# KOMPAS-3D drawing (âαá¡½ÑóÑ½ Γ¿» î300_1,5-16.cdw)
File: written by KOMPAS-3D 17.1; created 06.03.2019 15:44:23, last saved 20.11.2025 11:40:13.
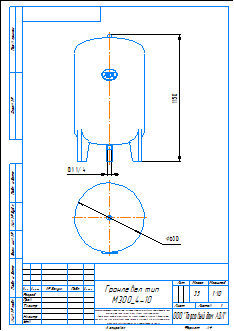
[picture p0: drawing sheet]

Sheet 1: A4, portrait

Title block, sheet 1: name: Гранлевел тип / М300_4-10; mass: 35; sheets: 1; sheet format: A4; stored path: C:\Users\kka\KOMPAS_Work\!Trash\ГРАНЛЕВЕЛ тип А Расширительный бак\KOMPAS 2D\Гранлевел тип А100_1,5-16.cdw

Views: Спереди 1, Спереди, Проекционный вид 2
Referenced files in C:\Users\mipv\Desktop\Тип А\SAT\: Гранлевел тип А300_4-10.a3d
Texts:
  kka
  adl
  Гранлевел тип А300_4-10
  Рама для чертежей
  Лит-Масса-Масштаб
  Материал-Предприятие
  Масштаб
  Изм.
  Лист
  № докум.
  Подп.
  Дата
  Лит.
  Разраб.
  Пров.
  Т.контр.
  Листов
  Внимание! Данный продукт является объектом авторского права ООО «Торговый Дом АДЛ».
  Запрещается изменение, копирование, распространение
  (в том числе путем копирования на другие сайты и ресурсы в Интернете)
  или любое иное использование информации и объектов без предварительного
  согласия правообладателя (ООО «Торговый Дом АДЛ»).
  Н.контр.
  Утв.
  ООО "Торговый дом АДЛ"
  Изменение
  Номер документа
  Подпись
  Обозначение документа
  Наименование изделия
  Масса изделия по ГОСТ 2.109-73
  Порядковый номер листа
  Общее количество листов в документе
  Характер работы, выполненной лицом, подписавшим документ
  Наименование или индекс предприятия, выпускающего документ
  Инв. № подл.
  Подп. и дата
  Взам. инв. №
  Инв. № дубл.
  Инвентарный номер подлинника по ГОСТ 2.501-68
  Подпись принявшего подлинник в отдел технической документации
  Инвентарный номер подлинника, взамен которого выпущен данный подлинник
  Инвентарный номер дубликата по ГОСТ 2.502-68
  Подпись принявшего дубликат в отдел технической документации
  Справ. №
  Перв. примен.
  Обозначение документа, взамен или на основании которого выпущен данный документ
  Обозначение документа, в котором впервые записан данный документ
  Подпись лица, копировавшего чертеж
  Обозначение формата листа
  !Рама для чертежа
Dimensions and other numbers on the sheet: 1150; 630; 1:10; 1; 35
